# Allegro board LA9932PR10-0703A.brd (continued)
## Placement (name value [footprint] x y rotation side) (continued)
RC30  -  [R_0402]  107.06 112.4 270 top
RC31  -  [R0402_0OHM]  103.94 112.58 0 bottom
RC32  -  [R_0402]  110.62 111.48 90 top
RC33  -  [R0402_0OHM]  103.94 114.36 0 bottom
RC34  -  [R_0402]  111.51 111.48 90 top
RC35  -  [R0402_0OHM]  106.17 112.4 270 top
RC38  -  [R0402_0OHM]  140.34 111.36 90 top
RC40  -  [R0402_0OHM]  139.45 111.36 90 top
RC42  -  [R0402_0OHM]  141.23 111.36 90 top
RC44  -  [R0402_0OHM]  142.12 111.36 90 top
RC46  -  [R0402_0OHM]  143.89 111.36 90 top
RC48  -  [R0402_0OHM]  143 111.36 90 top
RC52  -  [R_0402]  106.17 114.18 270 top
RC53  -  [R_0402]  107.95 112.4 270 top
RC54  -  [R_0402]  110.62 114.56 270 top
RC55  -  [R_0402]  104.26 100.64 0 bottom
RC56  -  [R_0402]  104.85 113.47 180 bottom
RC57  -  [R_0402]  111.51 114.56 270 top
RC58  -  [R_0402]  112.52 68.71 270 top
RC59  -  [R_0402]  103.94 111.69 0 bottom
RC60  -  [R_0402]  105.17 96.83 180 bottom
RC61  -  [R_0402]  110.74 68.71 270 top
RC62  -  [R_0402]  109.73 112.4 270 top
RC63  -  [R_0402]  111.63 68.71 270 top
RC64  -  [R_0402]  104.27 98.66 90 bottom
RC66  -  [R0402_0OHM]  103.38 99.57 270 bottom
RC67  -  [R_0402]  104.26 97.72 0 bottom
RC68  -  [R_0402]  149.72 88.76 0 bottom
RC69  -  [R_0402]  150.63 89.65 180 bottom
RC73  -  [R_0402]  138.82 97.08 90 top
RC74  -  [R_0402]  134.64 113.28 180 top
RC75  -  [R_0402]  138.69 117.1 270 top
RC76  -  [R_0402]  105.17 94.23 180 top
RC77  -  [R_0402]  105.17 95.81 180 bottom
RC78  -  [R_0402]  105.17 95.11 180 top
RC79  -  [R_0402]  105.16 99.57 270 bottom
RC80  -  [R_0402]  129.48 112.12 90 top
RC81  -  [R_0402]  105.17 101.53 180 bottom
RC82  -  [R_0402]  138.42 99.43 0 top
RC83  -  [R_0402]  105.17 93.34 180 top
RC85  -  [R_0402]  151.77 97.12 180 top
RC86  -  [R_0603]  152.83 98.52 270 top
RC87  -  [R_0402]  107.96 115.05 180 top
RC88  -  [R_0402]  105.27 115.05 0 top
RC89  -  [R_0402]  150.85 98.01 0 top
RC90  -  [R_0402]  107.96 115.94 180 top
RC91  -  [R_0402]  101.72 115.31 0 bottom
RC92  -  [R0402_0OHM]  104.85 115.31 180 bottom
RC93  -  [R0402_0OHM]  104.85 116.2 180 bottom
RC94  -  [R_0402]  102.63 116.2 180 bottom
RC99  -  [R_0603]  104.97 111.56 90 top
RC100  -  [R_0402]  105.17 96 180 top
RC103  -  [R0402_0OHM]  106.55 51.67 90 top
RC104  -  [R_0402]  106.69 47.62 180 top
RC105  -  [R0603_0OHM]  152.21 96.38 90 bottom
RC106  -  [R_0603]  149.67 97.65 0 bottom
RC108  -  [R_0402]  89.46 25.45 0 top
RC109  -  [R_0402]  95.2 26.03 180 top
RC110  -  [R_0402]  99.14 23.74 180 top
RD1  -  [R0402_0OHM]  92.65 33.19 90 top
RD2  -  [R_0402]  100.9 26.77 90 top
RD3  -  [R_0402]  91.76 33.19 90 top
RD4  -  [R0402_0OHM]  100.01 27.69 270 top
RD5  -  [R_0402]  136.92 21.96 180 top
RD6  -  [R0402_0OHM]  151.63 35.68 0 top
RD7  -  [R0402_0OHM]  152.39 32.95 0 top
RD8  -  [R0402_0OHM]  93.79 21.88 90 top
RD9  -  [R_0402]  92.78 22.2 90 top
RD10  -  [R_0402]  132.4 11.98 90 top
RD11  -  [R0402_0OHM]  152.66 23.05 270 top
RD12  -  [R0402_0OHM]  153.43 18.96 90 top
RD13  -  [R0402_0OHM]  135.07 22.9 90 top
RD14  -  [R_0402]  94.68 22.8 270 top
RD15  -  [R_0402]  96.47 22.79 180 top
RD16  -  [R_0402]  95.56 21.9 0 top
RD17  -  [R_0402]  93.41 26.9 90 top
RD18  -  [R_0402]  92.99 28.69 0 top
RD19  -  [R_0402]  95.2 27.8 180 top
RD20  -  [R_0402]  102.15 24.55 270 top
RD21  -  [R_0402]  103.04 22.77 270 top
RD22  -  [R_0402]  103.04 24.55 270 top
RD23  -  [R0402_0OHM]  131.51 11.98 90 top
RD24  -  [R_0402]  99.24 24.63 0 top
RD25  -  [R0402_0OHM]  101.82 27.69 270 top
RD26  -  [R0402_0OHM]  91.62 26.98 0 top
RD27  -  [R_0402]  91.58 27.87 180 top
RD28  -  [R_0402]  97.35 21.57 90 top
RD29  -  [R0402_0OHM]  102.15 21.86 90 top
RD30  -  [R_0402]  89.21 21.9 0 top
RD31  -  [R0402_0OHM]  89.47 23.69 270 top
RE3  -  [R0402_0OHM]  192.14 12.94 0 top
RE4  -  [R0402_0OHM]  192.14 13.96 0 top
RE7  -  [R_0402]  119.57 157.76 270 bottom
RE8  -  [R_0402]  120.46 157.76 270 bottom
RE9  -  [R_0402]  121.35 157.76 270 bottom
RE10  -  [R_0402]  122.24 157.76 270 bottom
RE13  -  [R_0402]  123.13 157.76 270 bottom
RE14  -  [R_0402]  124.02 157.76 270 bottom
RE15  -  [R_0402]  124.91 157.76 270 bottom
RE16  -  [R_0402]  125.79 157.76 270 bottom
RE17  -  [R_0402]  119.61 169.89 270 top
RE18  -  [R_0402]  120.5 169.89 270 top
RE19  -  [R_0402]  121.39 169.89 270 top
RE20  -  [R_0402]  122.28 169.89 270 top
RE21  -  [R_0402]  123.17 169.89 270 top
RE22  -  [R_0402]  124.06 169.89 270 top
RE23  -  [R_0402]  124.94 169.89 270 top
RE24  -  [R_0402]  125.83 169.89 270 top
RE25  -  [R0402_0OHM]  192.14 15.1 0 top
RE26  -  [R0402_0OHM]  192.14 16.12 0 top
RE27  -  [R0402_0OHM]  195.31 30.93 0 top
RE28  -  [R0402_0OHM]  195.31 32.07 0 top
RH3  -  [R_0402]  215.6 108.03 180 bottom
RH4  -  [R_0402]  215.6 107.01 180 bottom
RH5  -  [R_0402]  177.42 127.04 90 top
RH6  -  [R_0402]  215.6 106 180 bottom
RH7  -  [R_0402]  215.6 104.98 180 bottom
RH8  -  [R_0402]  215.6 103.97 180 bottom
RH9  -  [R_0402]  215.6 102.95 180 bottom
RH10  -  [R_0402]  215.6 100.92 180 bottom
RH11  -  [R_0402]  202.36 108.67 0 bottom
RH12  -  [R_0402]  202.36 106.63 0 bottom
RH13  -  [R_0402]  202.36 107.65 0 bottom
RH14  -  [R_0402]  202.36 105.62 0 bottom
RH16  -  [R_0402]  202.36 104.6 0 bottom
RH17  -  [R_0402]  215.6 101.93 180 bottom
RH19  -  [R_0402]  202.36 103.59 0 bottom
RH20  -  [R_0402]  202.36 102.57 0 bottom
RH22  -  [R_0402]  202.36 101.55 0 bottom
RH24  -  [R_0402]  203.28 110.7 180 bottom
RH25  -  [R_0402]  202.36 109.68 0 bottom
RH26  -  [R_0402]  215.6 99.9 180 bottom
RH27  -  [R_0402]  202.36 99.14 0 bottom
RH28  -  [R_0402]  215.6 98.89 180 bottom
RH30  -  [R_0402]  215.6 97.87 180 bottom
RH31  -  [R_0402]  215.6 96.85 180 bottom
RH32  -  [R_0402]  203.28 97.11 180 bottom
RH34  -  [R_0402]  164.04 133.34 180 top
RH35  -  [R_0402]  184.33 136.48 180 bottom
RH37  -  [R_0402]  157.61 120.69 90 bottom
RH38  -  [R0402_0OHM]  182.64 125.53 180 top
RH39  -  [R_0402]  180.85 125.99 270 top
RH40  -  [R_0402]  177.92 137.72 0 top
RH42  -  [R_0402]  179.71 127.04 90 top
RH43  -  [R_0402]  181.63 131.63 180 bottom
RH44  -  [R_0402]  178.82 127.04 90 top
RH45  -  [R_0402]  186.18 136.48 180 bottom
RH46  -  [R_0603]  166.19 118.27 90 top
RH47  -  [R_0402]  167.26 124.02 270 bottom
RH48  -  [R_0402]  165.55 120.88 90 top
RH50  -  [R_0402]  166.5 120.88 90 top
RH51  -  [R0402_0OHM]  156.21 129.28 0 top
RH52  -  [R_0402]  164.72 123.17 90 top
RH53  -  [R0402_0OHM]  175.11 130.6 90 top
RH54  -  [R_0402]  165.8 124.08 270 top
RH55  -  [R_0402]  166.75 124.08 270 top
RH56  -  [R_0402]  164.59 121.8 270 top
RH57  -  [R_0402]  157.12 128.39 180 top
RH66  -  [R0402_0OHM]  164.17 118.42 180 bottom
RH67  -  [R_0402]  183.01 130.53 90 bottom
RH70  -  [R_0402]  158.83 117.72 180 bottom
RH73  -  [R_0402]  170.96 117.45 90 top
RH75  -  [R_0402]  175.39 124.21 270 bottom
RH76  -  [R_0402]  161.8 121.67 270 top
RH78  -  [R_0402]  173.61 123.3 90 bottom
RH79  -  [R_0402]  177.17 123.3 90 top
RH80  -  [R_0402]  179.52 121.14 90 top
RH81  -  [R_0402]  181.63 130.47 180 bottom
RH85  -  [R_0402]  183 129.85 0 top
RH87  -  [R_0402]  181.61 125.45 90 bottom
RH88  -  [R_0402]  174.93 151.32 270 bottom
RH89  -  [R_0402]  174.04 151.32 270 bottom
RH90  -  [R_0402]  162.69 120.76 90 top
RH91  -  [R_0402]  177.17 124.21 270 bottom
RH92  -  [R_0402]  174.5 123.3 90 bottom
RH93  -  [R_0402]  157.91 118.61 0 bottom
RH94  -  [R_0402]  173.14 151.32 270 top
RH95  -  [R_0402]  173.14 151.32 270 bottom
RH96  -  [R0402_0OHM]  153.74 151.32 270 bottom
RH97  -  [R_0402]  169.5 146.1 90 top
RH98  -  [R0402_0OHM]  155.01 134.18 270 top
RH99  -  [R_0402]  154.63 151.32 270 bottom
RH100  -  [R_0402]  154.99 132.26 0 top
RH101  -  [R0402_0OHM]  180.8 123.69 180 bottom
RH102  -  [R0402_0OHM]  169.95 119.78 0 top
RH103  -  [R0402_0OHM]  183 130.74 0 top
RH104  -  [R0402_0OHM]  178.06 123.3 90 bottom
RH105  -  [R0402_0OHM]  176.28 123.3 90 top
RH106  -  [R0402_0OHM]  170.08 117.45 90 top
RH107  -  [R0402_0OHM]  176.28 123.3 90 bottom
RH108  -  [R0402_0OHM]  171.12 125.91 0 top
RH109  -  [R0402_0OHM]  156.72 120.69 90 top
RH110  -  [R0402_0OHM]  159.39 120.69 90 top
RH111  -  [R0402_0OHM]  160.28 120.69 90 top
RH112  -  [R_0402]  176.85 121.14 90 top
RH113  -  [R0402_0OHM]  158.5 120.69 90 top
RH114  -  [R0402_0OHM]  157.61 120.69 90 top
RH118  -  [R_0402]  176.99 142.87 180 top
RH119  -  [R_0402]  183 132.58 0 bottom
RH120  -  [R_0402]  177.74 121.14 90 top
RH146  -  [R_0402]  175.81 150.41 90 bottom
RH152  -  [R0402_0OHM]  159.56 152.77 0 bottom
RH153  -  [R_0402]  160.48 153.66 180 bottom
RH155  -  [R_0402]  179.97 148.65 180 bottom
RH157  -  [R_0402]  176.99 144.64 180 top
RH158  -  [R_0402]  181.41 145.72 0 top
RH159  -  [R_0402]  177 143.75 180 top
RH160  -  [R_0402]  182.68 149.66 0 bottom
RH162  -  [R_0402]  174.63 146.35 90 top
RH163  -  [R0402_0OHM]  161.72 147.31 90 top
RH164  -  [R_0402]  179.06 147.76 0 bottom
RH165  -  [R_0402]  159.83 150.09 90 bottom
RH170  -  [R_0402]  172.7 117.45 90 top
RH174  -  [R_0402]  169.04 112.36 90 top
RH175  -  [R_0402]  169.93 112.36 90 top
RH176  -  [R_0402]  152.6 147.25 180 bottom
RH177  -  [R0402_0OHM]  215.53 139.18 180 top
RH178  -  [R0402_0OHM]  215.53 137.91 180 top
RH179  -  [R0402_0OHM]  215.53 136.64 180 top
RH180  -  [R_0402]  237.73 130.42 0 top
RH181  -  [R0402_0OHM]  215.53 135.37 180 top
RH182  -  [R0402_0OHM]  215.53 134.1 180 top
RH183  -  [R0402_0OHM]  215.53 132.83 180 top
RH184  -  [R0402_0OHM]  215.53 131.56 180 top
RH185  -  [R0402_0OHM]  214.62 130.29 0 top
RH186  -  [R_0402]  237.73 123.56 0 top
RH187  -  [R_0402]  172.45 137.28 0 top
RH188  -  [R0402_0OHM]  152.97 140.18 0 bottom
RH192  -  [R_0402]  155.95 140.64 0 top
RH195  -  [R0402_0OHM]  159.7 127.19 270 top
RH196  -  [R0402_0OHM]  185.24 134.71 0 bottom
RH202  -  [R_0402]  183.91 131.63 180 top
RH206  -  [R_0402]  156.91 123.42 90 bottom
RH216  -  [R_0402]  184.27 134.71 180 bottom
RH222  -  [R_0402]  171.82 118.37 270 top
RH223  -  [R_0402]  171.31 116.39 0 top
RH224  -  [R_0402]  163.64 120.76 90 top
RH225  -  [R_0402]  162.63 124.08 270 bottom
RH226  -  [R_0402]  163.64 124.08 270 top
RH227  -  [R_0402]  162.69 121.67 270 bottom
RH228  -  [R_0402]  159.39 121.61 270 bottom
RH229  -  [R_0402]  163.64 120.76 90 bottom
RH230  -  [R_0402]  160.28 121.61 270 bottom
RH231  -  [R_0402]  163.58 124.08 270 bottom
RH232  -  [R_0402]  175.45 132.39 0 top
RH237  -  [R_0603]  182.18 135.76 180 bottom
RH238  -  [R0603_0OHM]  180.79 134.54 0 bottom
RH240  -  [R_0603]  184.33 127.18 90 top
RH241  -  [R0603_0OHM]  183.12 127.18 90 top
RH242  -  [R0805_0OHM]  182.97 137.79 180 top
RH244  -  [R0805_0OHM]  166.53 148.39 180 top
RH245  -  [R0805_0OHM]  177.89 139.82 180 top
RH246  -  [R0603_0OHM]  156.34 152.14 0 bottom
RH255  -  [R_0402]  170.37 147.01 270 top
RH256  -  [R_0402]  171.26 147.01 270 top
RH328  -  [R_0402]  181.63 132.58 180 bottom
RH330  -  [R_0402]  175.5 146.93 0 top
RH331  -  [R_0402]  152.57 127.08 0 top
RH332  -  [R_0402]  152.57 128.12 0 top
RP1  -  [RP_0804_8P4R]  173.17 156.51 180 bottom
RP2  -  [RP_0804_8P4R]  180.9 76.57 270 top
RP3  -  [RP_0804_8P4R]  195.84 69.98 180 top
RP4  -  [RP_0804_8P4R]  189.62 57.84 90 top
RP5  -  [RP_0804_8P4R]  186.64 76.38 90 top
RP6  -  [RP_0804_8P4R]  188.01 58.99 270 top
RP7  -  [RP_0804_8P4R]  208.33 91.37 270 top
RP8  -  [RP_0804_8P4R]  211.38 91.37 270 top
RP9  -  [RP_0804_8P4R]  220.72 75.92 0 top
RP10  -  [RP_0804_8P4R]  207.98 66.85 90 top
RP11  -  [RP_0804_8P4R]  236.48 72.14 180 top
RP12  -  [RP_0804_8P4R]  235.65 75.12 180 top
RP13  -  [RP_0804_8P4R]  212.33 144.27 270 top
RP14  -  [RP_0804_8P4R]  188.69 81.05 0 top
RP15  -  [RP_0804_8P4R]  198.21 66.18 90 top
RP16  -  [RP_0804_8P4R]  195.9 75.71 270 top
RP17  -  [RP_0804_8P4R]  214.39 91.37 270 top
RP18  -  [RP_0804_8P4R]  168.61 57.76 180 top
RP19  -  [RP_0804_8P4R]  168.57 63.02 180 top
RP20  -  [RP_0804_8P4R]  208.96 147.15 270 top
RPH1  -  [RP_0804_8P4R]  167.01 118.22 180 bottom
RPH3  -  [RP_0804_8P4R]  170.26 127.88 90 top
RPH4  -  [RP_0804_8P4R]  174.8 137.44 0 top
RPH5  -  [RP_0804_8P4R]  153.8 137.74 180 top
RPH6  -  [RP_0804_8P4R]  180.34 136.12 0 top
RPH7  -  [RP_0804_8P4R]  229.69 133.91 90 top
RPH8  -  [RP_0804_8P4R]  167.07 121.26 180 bottom
RPH9  -  [RP_0804_8P4R]  167.27 127.18 90 top
RPH10  -  [RP_0804_8P4R]  180.47 138.53 180 bottom
RPH11  -  [RP_0804_8P4R]  233.99 135.06 270 top
RPH12  -  [RP_0804_8P4R]  174.62 124.58 270 top
RPH13  -  [RP_0804_8P4R]  180.34 133.14 0 top
RPH14  -  [RP_0804_8P4R]  162.36 124.07 270 top
RPH15  -  [RP_0804_8P4R]  173.12 120.57 90 top
RPH16  -  [RP_0804_8P4R]  159.38 124.07 270 top
RPH17  -  [RP_0804_8P4R]  170.55 151.95 270 bottom
RPH18  -  [RP_0804_8P4R]  203.57 119.66 0 top
RPH19  -  [RP_0804_8P4R]  186.5 136.5 90 top
RPH20  -  [RP_0804_8P4R]  152.39 125.97 0 bottom
RPH21  -  [RP_0804_8P4R]  186.58 130.99 90 top
RPV1  -  [RP_0804_8P4R]  57.79 131.61 180 bottom
RV18  -  [R0402_0OHM]  77.97 147.31 0 bottom
RV25  -  [R_0402]  66.93 131.7 270 top
RV29  -  [R_0402]  82.68 148.25 90 top
RV33  -  [R_0402]  82.03 144.83 0 top
RV36  -  [R_0402]  79.32 129.28 225 top
RV41  -  [R_0402]  59.37 137.9 90 top
RV45  -  [R_0402]  61.6 135.58 270 top
RV46  -  [R_0402]  57.6 135.3 90 top
RV47  -  [R_0402]  91.75 125.72 0 top
RV48  -  [R_0402]  73.8 139.31 180 top
RV49  -  [R_0402]  58.49 137.99 270 top
RV52  -  [R_0402]  56.19 132.9 0 bottom
RV53  -  [R_0402]  92.66 124.83 180 top
RV55  -  [R_0402]  92.66 123.94 180 top
RV56  -  [R_0402]  89.97 123.05 0 top
RV57  -  [R_0402]  91.17 118.61 0 top
RV58  -  [R_0402]  89.28 118.81 270 top
RV59  -  [R_0402]  91.94 119.56 0 top
RV60  -  [R_0402]  90.17 117.9 90 top
RV61  -  [R_0402]  89.97 123.94 0 top
RV67  -  [R_0402]  94.06 94.8 180 top
RV76  -  [R0402_0OHM]  57.34 132.9 0 top
RV77  -  [R_0402]  90.88 125.72 180 top
RV78  -  [R_0402]  61.93 147.88 180 top
RV80  -  [R_0402]  86.43 86.3 270 top
RV81  -  [R_0402]  96.14 92.31 90 top
RV82  -  [R_0402]  100.48 93.35 270 top
RV88  -  [R_0402]  56.44 129.02 0 bottom
RV100  -  [R_0402]  79.19 149.01 90 bottom
RV103  -  [R_0402]  57.34 133.89 0 top
RV104  -  [R_0402]  89.97 124.83 0 top
RV107  -  [R_0402]  92.66 104.07 180 bottom
RV108  -  [R_0402]  92.66 106.74 180 top
RV109  -  [R_0402]  81.71 112.32 0 top
RV110  -  [R_0402]  92.65 104.94 90 top
RV111  -  [R_0402]  56.19 133.79 0 bottom
RV117  -  [R_0402]  55.87 104.38 0 bottom
RV118  -  [R_0402]  54.79 100.89 0 top
RV119  -  [R_0402]  64.21 94.29 180 top
RV120  -  [R_0402]  62.44 94.29 180 top
RV125  -  [R0402_0OHM]  80.14 150.94 270 bottom
RV128  -  [R_0402]  83.49 112.32 0 top
RV129  -  [R_0402]  82.92 93.4 0 top
RV131  -  [R_0402]  84.7 93.4 0 top
RV139  -  [R_0402]  92.65 103.17 90 top
RV140  -  [R_0402]  82.92 93.4 0 bottom
RV145  -  [R_0402]  84.22 129.59 180 top
RV146  -  [R_0402]  82.43 129.01 90 top
RV147  -  [R_0402]  83.53 127.35 270 top
RV148  -  [R_0402]  84.42 128.21 180 top
RV178  -  [R_0402]  59.32 124.96 180 top
RV179  -  [R_0402]  57.53 124.97 270 top
RV180  -  [R_0402]  60.69 125.91 0 top
RV181  -  [R_0402]  84.7 93.4 0 bottom
RV182  -  [R_0402]  84.41 88.13 180 top
RV183  -  [R_0402]  93.42 103.17 270 bottom
RV184  -  [R_0402]  93.42 101.41 270 bottom
RV185  -  [R_0402]  87.96 112.32 180 top
RV186  -  [R_0402]  86.18 112.32 180 top
RV187  -  [R_0402]  92.57 102.3 0 top
RV188  -  [R_0402]  92.57 101.41 0 top
RV189  -  [R_0402]  55.7 103.05 180 top
RV190  -  [R_0402]  55.7 102.16 180 top
RV191  -  [R_0402]  66.63 112.32 180 top
RV192  -  [R_0402]  64.84 112.31 90 top
RV193  -  [R_0402]  53.91 104.84 270 top
RV194  -  [R_0402]  54.8 103.93 90 top
RV195  -  [R_0402]  59.55 112.26 0 bottom
RV196  -  [R_0402]  61.34 111.36 90 bottom
RV197  -  [R_0402]  55.88 109.73 270 bottom
RV198  -  [R_0402]  56.71 107.04 90 bottom
RV203  -  [R_0402]  64.21 93.4 180 bottom
RV205  -  [R_0402]  62.44 93.4 180 bottom
RV237  -  [R_0402]  69.15 150.43 270 bottom
RV238  -  [R_0402]  69.22 147.23 90 bottom
RV239  -  [R_0402]  73.47 148.91 270 top
RV240  -  [R_0402]  73.47 147.13 270 top
RV241  -  [R_0402]  71.06 150.5 270 bottom
RV242  -  [R_0402]  71.25 147.23 90 bottom
RV243  -  [R_0402]  67.38 149.52 90 bottom
RV244  -  [R_0402]  68.26 150.43 270 bottom
RV296  -  [R_0402]  75.82 136.59 270 top
RV298  -  [R_0402]  75.83 137.47 180 top
SW1  -  [SW_SKRBAAE010_4P]  269.14 197.91 0 top
T2  -  [TPC12]  122.99 80.97 0 top
T3  -  [TPC12]  118.95 81.8 90 top
T4  -  [TPC12]  129.96 102.66 90 top
T5  -  [TPC12]  106.15 78.21 180 bottom
T6  -  [TPC12]  120.91 84.7 0 top
T7  -  [TPC12]  145.05 98.2 0 top
T8  -  [TPC12]  145.23 114.53 180 bottom
T9  -  [TPC12]  147.08 114.56 180 bottom
T10  -  [TPC12]  127.04 104.26 90 top
T11  -  [TPC12]  106.05 73.46 180 bottom
T12  -  [TPC12]  142.95 97.92 0 top
T13  -  [TPC12]  141.94 99.22 0 top
T14  -  [TPC12]  141.67 97.16 0 top
T15  -  [TPC12]  126.14 102.71 90 top
T16  -  [TPC12]  115.7 105.69 0 top
T17  -  [TPC12]  115.29 103.67 0 top
T18  -  [TPC12]  141.02 114.52 180 bottom
T19  -  [TPC12]  106.12 108.27 0 top
T20  -  [TPC12]  143.09 114.46 180 bottom
T22  -  [TPC12]  109.51 101.04 0 top
T23  -  [TPC12]  113.97 99.48 0 top
T24  -  [TPC12]  111.95 99.6 0 top
T25  -  [TPC12]  138.95 80.71 0 top
T26  -  [TPC12]  128.93 104.82 90 top
T27  -  [TPC12]  113.67 68.76 0 top
T28  -  [TPC12]  126.99 105.74 90 top
T29  -  [TPC12]  136.97 82.04 0 top
T30  -  [TPC12]  141 92.69 0 top
T31  -  [TPC12]  128.98 84.13 0 top
T32  -  [TPC12]  131.98 84.18 0 top
T33  -  [TPC12]  149.54 72.25 180 bottom
T34  -  [TPC12]  105.98 71.55 180 bottom
T35  -  [TPC12]  141.96 95.71 0 top
T36  -  [TPC12]  140.25 94.68 0 top
T39  -  [TPC12]  134.98 102.68 0 top
T40  -  [TPC12]  133.97 101.64 0 top
T41  -  [TPC12]  128.97 101.7 0 top
T42  -  [TPC12]  127.9 102.76 0 top
T43  -  [TPC12]  132.02 101.65 0 top
T44  -  [TPC12]  112.98 101.76 0 top
T45  -  [TPC12]  114.96 101.98 0 top
T46  -  [TPC12]  140.96 90.72 0 top
T48  -  [TPC12]  126.48 107.69 0 top
T49  -  [TPC12]  113.98 91.63 0 top
T50  -  [TPC12]  136.92 102.66 0 top
T51  -  [TPC12]  115.32 88.03 0 top
T52  -  [TPC12]  105.01 108.91 180 bottom
T53  -  [TPC12]  103.93 110.14 180 bottom
T54  -  [TPC12]  107.67 107.41 0 top
T55  -  [TPC12]  114.95 100.57 90 top
T56  -  [TPC12]  114.61 111.64 0 top
T57  -  [TPC12]  156.41 127.29 0 top
T58  -  [TPC12]  154.55 127.51 0 top
T59  -  [TPC12]  178 139.32 180 bottom
T60  -  [TPC12]  151.2 150.95 180 bottom
T61  -  [TPC12]  151.03 149.63 180 bottom
T62  -  [TPC12]  152.4 149.53 180 bottom
T63  -  [TPC12]  153.67 147.56 180 bottom
T64  -  [TPC12]  161.29 145.72 0 top
T65  -  [TPC12]  160.86 133.07 0 top
T66  -  [TPC12]  152.52 151.03 180 bottom
T67  -  [TPC12]  162.07 134.09 0 top
T68  -  [TPC12]  168.76 131.28 0 top
T71  -  [TPC12]  165.58 130.83 0 top
T72  -  [TPC12]  117.99 99.69 0 top
T75  -  [TPC12]  167.77 133.37 0 top
T76  -  [TPC12]  165.73 145.12 0 top
T77  -  [TPC12]  166.89 144.13 0 top
T78  -  [TPC12]  152.72 146.29 180 bottom
T79  -  [TPC12]  153.35 146.29 180 bottom
T80  -  [TPC12]  154.05 145.66 180 bottom
T81  -  [TPC12]  153.42 145.66 180 bottom
T82  -  [TPC12]  170.76 142.61 0 top
T83  -  [TPC12]  172.42 142.62 0 top
T84  -  [TPC12]  153.1 141.21 180 bottom
T85  -  [TPC12]  158.24 139.94 90 top
T86  -  [TPC12]  158.04 126.7 0 top
T87  -  [TPC12]  172.91 136.13 90 top
T88  -  [TPC12]  113.96 103.08 0 top
T89  -  [TPC12]  111.48 105.68 0 top
T90  -  [TPC12]  111.98 103.7 0 top
T105  -  [TPC12]  65.81 133.62 0 top
T106  -  [TPC12]  62.03 132.64 0 top
T108  -  [TPC12]  65.79 131.41 0 top
T116  -  [TPC12]  107.58 103.91 0 top
T117  -  [TPC12]  109.89 104.59 0 top
T118  -  [TPC12]  107.04 105.48 0 top
T122  -  [TPC12]  193.05 74.72 0 top
T131  -  [TPC12]  83.44 121.91 0 top
T132  -  [TPC12]  57.53 145.02 180 bottom
T133  -  [TPC12]  85.16 145.85 180 bottom
T142  -  [TPC12]  236.03 163.29 90 top
T143  -  [TPC12]  236.03 162.51 90 top
T146  -  [TPC12]  179.2 65.84 0 top
T147  -  [TPC12]  186.63 74.79 0 top
T151  -  [TPC12]  67.12 147.06 180 bottom
T152  -  [TPC12]  65.85 147.88 180 bottom
T156  -  [TAIMA_IH-115-F_24P]  259.26 187.43 90 top
T157  -  [TPC12]  108.61 94.47 0 top
T158  -  [TPC12]  110.01 94.91 0 top
T159  -  [TPC12]  108.55 99.49 0 top
T160  -  [TPC12]  106.11 97.78 180 bottom
T161  -  [TPC12]  111.93 94.49 0 top
T162  -  [TPC12]  106.64 99.55 0 top
T163  -  [TPC12]  106.58 102.61 0 top
T164  -  [TPC12]  107.44 101.07 0 top
T165  -  [TPC12]  108.45 102.56 0 top
T166  -  [TPC12]  105.7 100.74 0 top
T167  -  [TPC12]  108.65 96.18 0 top
T168  -  [TPC12]  108.79 98.2 0 top
T169  -  [TPC12]  111.96 95.9 0 top
T170  -  [TPC12]  106.66 98.06 0 top
T173  -  [TPC12]  108.89 105.9 0 top
T174  -  [TPC12]  112.98 104.82 0 top
U2  -  [SLGC55584AVTR_TDFN8_2X2]  275.07 185.01 180 top
U6  -  [PI3V713-AZLEX_TQFN32_6X3]  136.72 156.3 270 bottom
U8  -  [RT9818A-44GU3_SC70-3]  173.23 115.94 90 top
U9  -  [NL17SZ08DFT2G_SC70-5]  176.34 118.69 270 top
U15  -  [NL17SZ08DFT2G_SC70-5]  257.43 174.63 270 top
U19  -  [PS8401ATQFN40GTR-A3_TQFN40_5X5]  16.68 197.4 0 top
U20  -  [PI3C3125LEX_TSSOP14]  165.82 158.34 270 top
U21  -  [TC7SET04FU_SSOP5]  169.11 159.87 90 top
U23  -  [PI3C3125LEX_TSSOP14]  179.62 154.44 90 top
U24  -  [TC7SET04FU_SSOP5]  177.88 160.76 90 top
U27  -  [RTD2136S-CG_QFN48_6X6]  198.45 165.32 270 top
U31  -  [WGI217LM-QPN9-A2_QFN48_6X6]  243.2 161.68 90 top
U32  -  [PI3L720ZHEX_TQFN42_9X3P5]  246.26 177.4 0 top
U36  -  [TPS22966DPUR_SON14_2X3]  227.66 69.85 90 top
U37  -  [TPS22966DPUR_SON14_2X3]  173.55 41.26 0 top
U38  -  [OZ777FJ2LN_QFN48_6X6]  183.34 28.86 270 top
U39  -  [AT97SC3204-X2A14-AB_TSSOP28]  217.21 113.19 180 top
U41  -  [TPS2231MRGPR-2_QFN20_4X4]  235.63 64.96 180 top
U46  -  [ECE5048-LZY_DQFN132_11X11]  191.32 64.06 90 top
U48  -  [G547I2P81U_MSOP8]  281.66 192.24 0 top
U50  -  [NL17SZ08DFT2G_SC70-5]  200.02 89.26 90 top
U51  -  [MEC5075-LZY_DQFN132_11X11]  205.93 73.34 0 top
U52  -  [W25Q64FVSSIQ_SO8]  235.47 127.88 90 top
U53  -  [W25Q32FVSSIQ_SO8]  235.47 121.76 90 top
U54  -  [NL17SZ08DFT2G_SC70-5]  217.17 157.39 90 top
U56  -  [NL17SZ08DFT2G_SC70-5]  214.25 154.53 90 top
U57  -  [TPS22966DPUR_SON14_2X3]  245.31 148.96 0 top
U58  -  [NL17SZ08DFT2G_SC70-5]  227.27 113.06 270 top
U74  -  [ALC3226-CG_QFN48_7X7]  267.99 159.97 270 top
U88  -  [LNG3DMTR_LGA16_3X3]  83.65 51 0 top
U89  -  [AP2330W-7_SC59-3]  25.47 204.46 90 top
U91  -  [G547I2P81U_MSOP8]  282.17 181.88 270 top
U93  -  [G547I2P81U_MSOP8]  279.12 169.43 270 top
U145  -  [TPS22966DPUR_SON14_2X3]  264.05 175.69 0 top
U146  -  [TPS22966DPUR_SON14_2X3]  220.67 126.47 90 top
U148  -  [APL3512ABI-TRG_SOT23-5]  196.66 172.35 180 top
UC1  -  [74AHC1G09GW_TSSOP5]  104.13 48.94 0 top
UC2  -  [SN74LVC1G07DCKR_SC70-5]  101.45 95.53 90 bottom
UC3  -  [74AHC1G09GW_TSSOP5]  160.15 116.94 90 bottom
UH1  -  [DH82LPMS-QCG1-B0_FCBGA_695P]  175.8 128.04 90 bottom
UH2  -  [NL17SZ08DFT2G_SC70-5]  179.27 127.34 0 bottom
UH3  -  [NL17SZ08DFT2G_SC70-5]  160.28 119.58 270 top
UV1  -  [216-0841009-A0-SUN_FCBGA_631P]  60.58 123.4 0 bottom
UV3  -  [K4G41325FC-HC04_FBGA_170P]  69.46 96.46 180 top
UV4  -  [K4G41325FC-HC04_FBGA_170P]  79 109.26 0 top
UV5  -  [K4G41325FC-HC04_FBGA_170P]  79 96.46 0 bottom
UV6  -  [K4G41325FC-HC04_FBGA_170P]  69.46 109.26 180 bottom
UV14  -  [74AHC1G09GW_TSSOP5]  83.81 146.92 0 top
Y3  -  [Y_X3G025000DI1H-H_4P]  248.88 163.99 90 top
Y6  -  [Y_Q13FC1350000_2P]  198.71 72.63 0 top
YH1  -  [Y_Q13FC1350000_2P]  184.51 123.94 180 top
YH2  -  [Y_Q22FA2380049900_4P]  158.73 157.44 0 bottom
YV1  -  [Y_7V27000050_4P]  77.55 148.81 180 bottom

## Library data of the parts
C7 C1552 CC24-CC33 CC36-CC48 CH28 PC8 PC13 PC109 PC110 PC202 PC203 PC207 PC208 PC304 PC305 PC310 PC512-PC514 PC533-PC535 PC603 PC604 PC621 PC622 PC707 PC712-PC714 PC718 PC719 PC724 PC728 PC731 PC732 PC734 PC737-PC739 PC807 PC900-PC904 PC909-PC914 PC917-PC926 PC935-PC943 PC963-PC966 PC970-PC972 = C_0805
C8 C9 C16 C18 C25-C32 C46 C100 C101 C103-C105 C107 C108 C110-C112 C114 C116-C118 C283-C287 C290 C302 C306 C340 C342 C344 C354 C355 C399 C402 C416-C419 C435-C438 C444 C445 C448 C450 C451 C454 C482 C500 C501 C580 C581 C628-C631 C636 C675 C724 C740 C757 C774-C777 C780 C781 C800 C802 C968 C972 C998 C1002 C1004 C1107 C1167 C1184 C1216 C1501 C1503 C1505 C1506 C1508-C1510 C1518 C1519 C1524 C1526 C1533 C1534 C1539 C1541 C1551 C1553-C1559 CC17-CC19 CC21 CC138 CD45-CD48 CE5 CE7 CE10-CE18 CH6 CH7 CH10-CH14 CH17 CH22-CH25 CH27 CH29 CH37 CH40 CH53 CH76 CV18-CV26 CV52 CV54 CV57 CV61 CV62 CV67 CV71 CV75 CV80 CV82 CV83 CV92-CV95 CV151-CV159 CV162-CV164 CV166 CV167 CV182 CV185 CV199 CV203 CV204 CV215 CV219 CV220 CV222 CV223 CV225 CV322-CV333 CV340-CV344 CV349-CV358 CV411 PC5 PC17 PC103 PC105 PC106 PC205 PC209 PC211 PC214 PC215 PC302 PC303 PC307 PC401 PC402 PC405-PC407 PC500 PC510 PC515 PC516 PC518 PC520 PC521 PC525-PC528 PC536 PC539-PC541 PC545-PC548 PC600 PC602 PC611-PC616 PC624 PC627 PC630 PC632 PC665-PC668 PC674 PC675 PC704 PC705 PC708 PC710 PC716 PC721-PC723 PC725-PC727 PC729 PC730 PC733 PC736 PC801 PC805 PC808-PC810 PC812 PC814 PC817 PC927-PC934 PC944-PC951 = C_0402
C44 C45 C550-C553 = C_0402: room: TPM
C47 C106 C109 C113 C115 C246 C247 C423 C439 C443 C446 C447 C449 C452 C453 C455 C479-C481 C483 C484 C578 C639 C676 C779 C782 C783 C967 C969 C1214 C1247 C1502 C1504 C1507 C1525 C1540 CC137 CD12 CH20 CH21 CH38 CV56 CV58-CV60 CV66 CV84 CV98 CV201 CV216 CV221 CV224 CV274 CV275 CV423 PC3 PC12 PC14 PC111 PC112 PC114 PC116-PC120 PC206 PC210 PC212 PC213 PC306 PC308 PC309 PC400 PC403 PC404 PC509 PC511 PC522 PC524 PC529 PC538 PC542 PC543 PC601 PC605 PC607 PC608 PC610 PC617-PC619 PC623 PC626 PC631 PC660-PC664 PC669 PC670 PC672 PC680 PC700 PC703 PC706 PC709 PC715 PC717 PC720 PC735 PC811 PC813 PC815 PC816 PC818-PC820 = C_0603
C50 C1001 = C_0402: room: IO
C51-C53 = C_0402: room: USH
C288 C289 C720-C722 C725 C727 C733-C737 C739 C741-C744 = C_0402: room: KBC
C296 = C_0603: room: LVDS
C297 C298 = C_0402: room: LVDS
C299 C301 = C_0402: room: CAM
C300 = C_0603: room: CAM
C346-C353 = C_0402: room: HDMI
C356 C357 C360 C365-C369 = C_0402: room: DP_SW
C383-C386 C388 C395 C396 = C_0402: room: HDD
C387 = C_0603: room: HDD
C397 C398 C404-C409 = C_0402: room: ODD
C458-C461 C463 C466-C474 C478 = C_0402: room: LAN
C462 C464 = C_0603: room: LAN
C485 = C_1808
C559-C561 C564 C566 C572 C577 = C_0603: room: OZ600
C567-C569 C571 C574-C576 = C_0402: room: OZ600
C595 C596 C598 C603-C607 = C_0402: room: WLAN
C608 = C_0603: room: WLAN
C610-C612 C614 = C_0402: room: WWAN
C613 = C_0805: room: WWAN
C615 = C_D2: room: WWAN
C616 = C_0402: room: SIM
C617 C618 C621-C625 = C_0402: room: WPAN
C626 = C_0603: room: WPAN
C633-C635 C637 C640 C642 C645 C646 C649 = C_0402: room: EXPRESS
C638 C641 C643 = C_0603: room: EXPRESS
C651 = C_APXK6R3ARA221MF451: room: USB
C654 C715 = C_0402: room: USB
C679-C701 = C_0402: room: DOCKING
C702 C703 = C_0603: room: DOCKING
C705 C714 = C_0603: room: SIO
C706-C710 C716 = C_0402: room: SIO
C746 = C_0402: room: FLASH ROM
C755 C759 = C_0402: room: TOUCH.PAD
C756 C758 = C_0402: room: KB
C764 = C_0603: room: +3V_5V_RUN SOURCE
C765 = C_0603: room: +3.3V_SUS SOURCE
C772 = C_0603: room: +1.05VRUN_SOURCE
C773 = C_0402: room: +1.05VRUN_SOURCE
C778 = C_0402: room: LED
C952 C954-C956 C962 C963 C965 = C_0603: room: CODEC
C957 C959 C961 C973-C977 C994 C1105 C1106 = C_0402: room: CODEC
C958 C960 = C_0805: room: CODEC
C1177 C1178 = C_0805: room: LAN
C1523 C1538 = C_B2
CC1-CC16 = C_0402: room: CPU
CC34 CC35 PC606 PC628 PC629 PC677 = C_D2
CD1-CD6 CD15-CD28 CD37-CD44 = C_0402: room: MEMORY
CD7-CD11 CD13 CD29-CD35 = C_0603: room: MEMORY
CD14 CD36 = C_APXK2R5ARA331MF451: room: MEMORY
CE6 = C_0805: room: DOCKING
CH2 CH4 CH5 CH18 CH19 CH30 CH34-CH36 CH43-CH51 CH54-CH57 CH59-CH62 CH64-CH75 = C_0402: room: PCH
CH52 CH63 = C_0603: room: PCH
CMOS1 ME1 = SHORTPADS: User Part Number: PART#; room: PCH
CV1-CV17 CV49 CV53 CV55 CV68 CV69 CV73 CV74 CV76-CV79 CV81 CV85-CV87 CV129-CV131 CV133 CV134 CV137-CV150 CV165 CV176-CV181 CV188 CV189 CV191 CV192 CV198 CV207-CV210 = C_0402: room: GPU
CV41-CV44 CV70 CV72 CV202 = C_0603: room: GPU
D1 D35 D36 D71 = RB751V40_SC76-2
D7 D9 D10 = BAT54CW_SOT323-3
D31 = RB751V40_SC76-2: room: WLAN
D32 = RB751V40_SC76-2: room: DOCKING
D33 = L30ESD24VC3-2_SOT23-3: room: DOCKING
D59 D62 = RB751V40_SC76-2: room: LED
D72 = L30ESDL5V0C3-2_SOT23-3: room: USB
D78 = TVWDF1004AD0_DFN9: room: USB
D81 D82 = L03ESDL5V0CC3-2_SOT23-3
D86 = PESD5V0U2BT_SOT23-3
D88 D91 = TVWDF1004AD0_DFN9
D89 D90 = L30ESDL5V0C3-2_SOT23-3
FD1-FD4 = FIDUCIAL_C40M80: room: LED
H1 H2 = H_3P8: room: LED
H3 H5 H6 H9 H15 H16 = H_3P3: room: LED
H4 H8 H10 H12 H13 = H_3P0: room: LED
H7 H11 H20 = H_3P0
H14 = H_3P2: room: LED
H17 = H_2P0N: room: LED
H18 H19 = H_2P3
H21 = H_3P1X2P1N
H22 H23 = H_3P3
JAPS1 = TYCO_1-2041070-6_16P
JCAM1 = E-T_3702K-Q08C-07L_8P: room: CAM
JCPU1 = LOTES_AZIF0012-P002B_947P-T: room: CPU
JDEG2 = HB_A531015-SCHR21_10P: room: KBC
JDIMM1 = TYCO_2-2013290-1_204P: room: MEMORY
JDIMM2 = TYCO_2-2013311-1_204P: room: MEMORY
JDOCK1 = JAE_WD2F144WB1R300_144P: room: DOCKING
JEXP1 = E-T_1001K-F30C-03L_30P-T: room: EXPRESS
JFAN1 = ACES_50273-0040N-001_4P: room: FAN
JHDMI1 = CONCR_099ATAC19NBLCNF_19P: room: HDMI
JHP1 = SINGA_2SJ3082-000111F_6P-T
JIO1 = E-T_1000K-Y40E-02L_40P: room: IO
JKB1 = HB_A091020-SAHR22_10P: room: KB
JLED1 = HB_A520620-SCHR22_6P
JLOM1 = J-L_TNBNRBC80002008_13P-T
JLVDS1 = ACES_59003-04006-001_40P
JMDIA1 = HB_A520620-SCHR22_6P: room: IO
JMINI1 = BELLW_80003-8041_52P
JMINI2 = BELLW_80003-8041_52P: room: WLAN
JMINI3 = BELLW_80003-1121_52P: room: WPAN
JRTC1 = ACES_50273-0020N-001_2P
JSATA1 = SANTA_196003-1_22P: room: HDD
JSATA2 = TYCO_2-2129116-3_31P-T: room: ODD
JSD1 = ALPS_SCDACA0101_19P: room: OZ600
JSF1 = HB_A090620-SAHR21_6P
JSIM1 = T-SOL_159-1000302602_10P-T: room: SIM
JSPI1 = TYCO_2-2041070-0_20P-T: room: FLASH ROM
JSPK1 = ACES_50273-0040N-001_4P: room: CODEC
JTAG1 = SHORTPADS: User Part Number: PART#; room: KBC
JTCH1 = ACES_50228-0067N-001_6P
JTP1 = HB_A520820-SCHR22_8P: room: TOUCH.PAD
JUSB1 = SANTA_373130-1_9P: room: USB
JUSB2 = LOTES_ABA-USB-116-P04_9P: room: USB
JUSB3 = LOTES_ABA-USB-116-P04_9P
JUSH1 = HB_A522020-SCHR22_20P: room: USH
JXDP1 = MOLEX_52435-2671_26P-T: room: XDP1
JXDP2 = SAMTE_BSH-030-01-L-D-A_60P: room: XDP2
L1-L4 L99 L108 L109 L111 L112 LE2 LE4 LE5 = MURAT_DLW21SN900HQ2L_0805_4P
L10 = MURAT_DLW21SN121SQ2L_4P: room: CAM
L11 L107 L110 = MURAT_DLW21SN900SQ2L_0805_4P
L13 = MURAT_BLM15BB221SN1D_2P
L29 = TAIYO_CBC2012T4R7M_2P: room: LAN
L45 L47 = MURAT_BLM15BD601SN1D_2P: room: OZ600
L51 = MURAT_DLW21SN900SQ2L_0805_4P: room: USB
L77 = MURAT_BLM15PX600SN1D_2P: room: CODEC
L95 L96 = MURAT_DLW21SN900HQ2L_0805_4P: room: USB
L702-L705 = MURAT_BLM18PG330SN1D_2P
L706 L707 = MURAT_BLM15BD601SN1D_2P
LED1 = LED_LTW-193ZDS5_2P: room: LED
LH1 = MURAT_BLM18PG181SN1D_2P: room: PCH
LV16-LV19 LV21 LV30 PH500 PH501 PH600 PH601 PR1 PR6 PR10-PR16 PR18 PR20 PR23 PR25 PR100-PR102 PR104-PR106 PR111 PR119 PR201 PR204-PR207 PR209 PR300 PR302 PR303 PR305-PR307 PR402 PR403 PR405 PR500 PR503 PR504 PR507 PR509 PR512 PR519 PR521 PR525 PR528-PR530 PR533 PR535 PR537 PR539 PR543-PR546 PR549 PR551 PR555 PR556 PR558 PR602 PR604 PR605 PR607 PR608 PR610 PR612 PR615 PR616 PR619 PR623 PR624 PR626 PR627 PR631-PR634 PR638-PR640 PR642 PR644 PR645 PR648 PR651 PR652 PR654-PR656 PR659 PR683 PR684 PR687 PR689 PR691 PR692 PR697 PR703 PR706 PR707 PR713 PR714 PR720 PR722 PR723 PR725-PR728 PR730-PR736 PR738-PR741 PR743 PR744 PR746-PR748 PR801 PR802 PR804 PR807 PR808 PR810 PR813-PR819 PR822-PR824 PR826-PR830 PR833 PR834 PR839 PR840 PR844 PR846 PR849 PR858 PR863 PR864 PR869 PR870 PR874 PR875 PR881 PR883-PR885 PR894 R7 R30 R38 R39 R51 R52 R55 R61-R65 R68-R82 R85-R88 R100 R101 R105-R108 R114 R153 R392 R407 R415 R424 R431-R433 R517 R558 R566 R571-R574 R657 R695 R806 R864 R874 R888 R952 R1069 R1088 R1100 R1119 R1120 R1139 R1141 R1142 R1145 R1146 R1166 R1167 R1624 R1629 R1630 R1635 R1636 R1640 R1642 R1653 R1654 R1667 R1668 R1676 R1677 R1679 R1700 R1702 R1703 R3664-R3666 R3668 R3669 R3671 R3689-R3691 R3696-R3698 R3710 R3711 R3721 R3722 R3727 R3728 R3737 R3761 R3771 R3773 R3884-R3886 RC11-RC13 RC20-RC22 RC30 RC34 RC55 RC58 RC59 RC62 RC69 RC75-RC77 RC80 RC81 RC83 RC85 RC87-RC91 RC94 RC104 RC108-RC110 RD9 RD10 RD14 RD16-RD22 RD24 RD27 RD28 RD30 RE7-RE10 RE13-RE24 RH32 RH34 RH37 RH54-RH57 RH67 RH70 RH73 RH81 RH85 RH88-RH90 RH92 RH93 RH95 RH119 RH146 RH153 RH155 RH157 RH159 RH162 RH165 RH175 RH176 RH180 RH186 RH187 RH192 RH202 RH206 RH216 RH222-RH232 RH255 RH328 RH330-RH332 RV25 RV48 RV81 RV82 RV88 RV100 RV103 RV104 RV128 RV129 RV131 RV139 RV140 RV145-RV148 RV178-RV198 RV203 RV205 RV237-RV244 RV296 RV298 = R_0402
PBATT1 = OCTEK_BTJ-09WKFB_9P
PC101 PC102 = C_APXK6R3ARA221MF451
PC201 PC301 = C_APXK2R5ARA331MF451
PC216 = C_SX
PC530-PC532 = C_EEEFK1E101YP
PC905-PC908 PC916 = C_D1
PD2 PD4 = TVNST52302AB0_SOT523-3
PD3 = BAS40-05W_SC70-3
PD7 PD807 PD811 PD818-PD821 = SDMK0340L-7-F_SOD323-2
PD700 = SBR3A40SA-13_SMA2
PD701 PD810 PD813 PD815 = RB717F_SOT323-3
PD702 = RB751V-40_SOD323-2
PD800 PD806 PD808 = PDS5100H-13_POWERDI5-3
PJP1 PJP101-PJP103 PJP200 PJP203 PJP204 PJP301 PJP500 PJP600 PJP700 = JUMP_43X118
PJP2 PJP63 PJP67 PJP201 PJP202 PJP602 PJP701 = JUMP_43X39
PJP3 = JUMP_43X79: room: +5V_HDD SOURCE
PJP4 = JUMP_43X79: room: +5VMOD SOURCE
PJP53 PJP64 = JUMP_43X39: room: HDD
PJP60 PJP100 PJP300 PJP400 PJP401 PJP609-PJP612 PJP702 = JUMP_43X79
PJP61 = JUMP_43X39: room: TPM
PJP62 PJP65 = JUMP_43X39: room: CODEC
PJPDC1 = JESS_UCNR2451M005-0_5P
PL2 PL3 = TAIYO_FBMJ4516HS720NT_2P
PL4 = MURAT_BLM15AG102SN1D_2P
PL5 = KC_FBMA-L18-453215_L1812_2P
PL101 = CYNTE_PCMB063T-2R2MS_2P
PL102 = CYNTE_PCMB063T-3R3MS_2P
PL103 PL701 = CYNTE_PCMB053T-1R0MS_2P
PL201 = TOKO_FDUE1040D-1R0M-P3_2P
PL301 = TOKO_FDSD0630-H-1R0M-P3_2P
PL401 = CYNTE_PH041H-1R0MS_2P
PL502 PL503 PL600 PL601 = NEC_MPC0740LR42C_2P
PL504 PL602 = L_1812-1806
PL603 = TOKO_FDSD0420-H-1R0M-P3T_2P
PL700 = TOKO_FDVE1040-H-5R6M-P3_2P
PQ1 PQ816 = FDV301N_NL_SOT23-3
PQ2 = MMST3904-7-F_SOT323-3
PQ4 PQ810 PQ811 PQ815 PQ826 = FDS6679AZ_SO8
PQ6 = IMD2AT-108_SC74-6
PQ7 PQ801 PQ814 PQ822 PQ823 PQ828 PQ830 = FDN338P_NL_SOT23-3
PQ101 PQ102 PQ301 = SIS412DN-T1-GE3_POWERPAK8-5
PQ103 PQ104 PQ303 = SI7716ADN-T1-GE3_POWERPAK8-5
PQ201 PQ505 PQ509 PQ704-PQ706 PQ711 = SIR472DP-T1-GE3_POWERPAK8-5
PQ203 = SIR818DP-T1_POWERPAK-SO8-5
PQ508 PQ512 = SI7170DP-T1-GE3_POWERPAK8-5
PQ600 PQ601 = CSD86350Q5D_SON8
PQ610 = SSM3K7002FU_SC70-3
PQ700 PQ800 PQ809 = SI4835BDY-T1-E3_SO8
PQ701 PQ702 = NTR4502PT1G_SOT23-3
PQ703 = NTGD4161PT1G_TSOP6
PQ707 PQ805-PQ807 PQ812 PQ813 PQ819 PQ821 PQ824 = 2N7002DW-T-R7_SOT363-6
PQ709 PQ710 PQ802 PQ817 PQ818 PQ825 PQ827 PQ829 PQ831 = RHU002N06_SOT323-3
PR22 PR401 PR680 PR835 = R_0805
PR26 PR103 PR110 PR118 PR208 PR210 PR211 PR308 PR309 PR406 PR511 PR520 PR524 PR526 PR548 PR600 PR618 PR620 PR621 PR625 PR628 PR629 PR635 PR643 PR650 PR657 PR681 PR688 PR700 PR702 PR704 PR705 PR709 PR710 PR717-PR719 PR724 PR737 PR745 PR811 PR812 PR832 PR838 PR843 PR847 PR850 PR857 PR862 PR866 PR868 PR882 PR886 PR887 PR890 PR895 R5 R6 R15 R40 R104 R152 R429 R575-R578 R830 R834 R839 R866 R1070 R1169 R1607 R1672 R1673 R3731 R3732 R3772 RC31 RC33 RC38 RC92 RC93 RC103 RD6 RD7 RD11-RD13 RD23 RD25 RD26 RD29 RD31 RE3 RE4 RE25-RE28 RH51 RH96 RH101 RH110 RH179 RH182 RH184 RH185 RH188 RH195 RH196 RV76 RV125 = R0402_0OHM
PR107 PR108 PR200 PR203 PR301 PR534 PR536 PR538 PR550 PR552 PR553 PR614 PR649 PR715 PR821 RC86 RC106 RH237 RH240 = R_0603
PR109 PR112 PR202 PR304 PR541 PR554 PR622 PR653 PR721 PR742 = R_1206
PR701 PR716 = R_1206_4P-D
PR831 PR854 PR877 R3881-R3883 RH242 RH244 RH245 = R0805_0OHM
PRP2 RP1-RP20 RPH1 RPH3-RPH21 RPV1 = RP_0804_8P4R
PU1 = TS5A63157DCKR_SC70-6
PU100 = TPS51225CRUKR_QFN20_3X3
PU200 = RT8207MZQW_WQFN20_3X3
PU300 = TPS51212DSCR_SON10_3X3
PU400 = SY8033BDBC_DFN10_3X3
PU500 = ISL95812HRZ-T_QFN32_4X4
PU600 = ISL62883CHRTZ-T_TQFN40_5X5
PU602 = SY8036DBC_DFN10_3X3
PU603 = G971ADJF11U_SO8
PU700 = BQ24738RGRR_QFN20_3P5X3P5
PU701 = LM393DR_SO8
PU703 = INA199A2DCKR_SC70-6
PU704 PU801 PU804-PU808 = TC7SH08FU_SSOP5
PU800 = CD3301RHHR_QFN36_6X6
Q1-Q4 QV7 = PMST3904_SOT323-3
Q21 = FDC654P-G_SSOT-6: room: LVDS
Q22 = L2N7002WT1G_SC-70-3: room: LVDS
Q23 = DMG2301U-7_SOT23-3: room: CAM
Q24 Q77 Q89 Q100 Q324 Q326 QC5 QD7 QD9 QH3 QV5 QV6 QV11 = L2N7002WT1G_SC-70-3
Q29 = DMN66D0LDW-7_SOT363-6: room: HDD
Q32 = PMV65XP_SOT23-3
Q45 Q47 = L2N7002WT1G_SC-70-3: room: KBC
Q48 = L2N7002WT1G_SC-70-3: room: USB
Q52 = DMN66D0LDW-7_SOT363-6: room: +1.5V_RUN_SOURCE
Q59 = L2N7002WT1G_SC-70-3: room: +1.5V_RUN_SOURCE
Q63 = AO4354_SOIC-8: room: +1.05VRUN_SOURCE
Q70-Q72 = L2N7002WT1G_SC-70-3: room: DISCHARGE
Q74 Q83 Q84 = DMN66D0LDW-7_SOT363-6: room: LED
Q75 Q79 Q81 = PDTA114EU_SC70-3: room: LED
Q76 Q123 = DMN66D0LDW-7_SOT363-6: room: ODD
Q106 = DMN66D0LDW-7_SOT363-6: room: CODEC
Q124 = DMN66D0LDW-7_SOT363-6: room: WLAN
Q325 Q330 Q331 QD6 = DMN66D0LDW-7_SOT363-6
QC1 = L2N7002WT1G_SC-70-3: room: CPU
QC3 = L2N7002WT1G_SC-70-3: room: +1.5V_CPU_VDDQ SOURCE
QH2 = BSS138W-7-F_SOT323-3: room: PCH
QH4 = DMN66D0LDW-7_SOT363-6: room: PCH
QV1 = AO4354_SOIC-8: room: GPU
QV2 = L2N7002WT1G_SC-70-3: room: GPU
QV3 QV8 = PMST3904_SOT323-3: room: GPU
QV4 = MMBT3906WT1G_SC70-3: room: GPU
QV12 = DMG2301U-7_SOT23-3
R154 R1658 R3735 R3736 R3762-R3770 RC105 RH238 RH241 RH246 = R0603_0OHM
R159 R160 R422 R423 R1137 R1138 = R_0402: room: LVDS
R416 = R_0402: room: CRT
R418 R420 R811 R812 R817 R825 R836 R843 R850 R871 R872 R875 R879 R884 R887 R1171 R1179 R1622 R1623 = R_0402: room: KBC
R427 R428 = R_0402: room: CAM
R491 R492 = R_0402: room: DP_SW
R501-R503 R506 R508 = R_0402: room: HDD
R512 = R_0402: room: +5VMOD SOURCE
R515 = R_0402: room: ODD
R545 R546 R549 R553 R557 R561 R562 = R_0402: room: LAN
R551 R552 R555 R1144 R1187 = R0402_0OHM: room: LAN
R585 R589 = R_0402: room: USH
R676 R677 = R_0402: room: OZ600
R693 R706 R1620 = R_0402: room: WLAN
R694 R719 R725 R726 = R_0402: room: WWAN
R703 R707 = R0402_0OHM: room: WLAN
R704 = R0402_0OHM: room: WWAN
R717 = R0402_0OHM: room: EXPRESS
R731 R732 R734 = R_0402: room: EXPRESS
R733 = R_0402: room: WPAN
R736 R740 R816 R1603-R1606 R1614 = R_0402: room: USB
R738 R802 = R0402_0OHM: room: SIO
R755 R757 R758 = R_0402: room: DOCKING
R772 R793 R796 R800 R803 R804 R807 R1154 = R_0402: room: SIO
R853 R1068 R1180 = R0402_0OHM: room: KBC
R894 R901 R936 = R_0402: room: FLASH ROM
R902 R903 = R_0402: room: TOUCH.PAD
R909 = R_0402: room: +1.5V_RUN_SOURCE
R925 R926 = R_0402: room: DISCHARGE
R927 = R_0603: room: DISCHARGE
R930 R931 R1611 = R_0402: room: +1.05VRUN_SOURCE
R932 R934 R937 R938 R949 R951 R953 R955 R957 R958 = R_0402: room: LED
R1076 R1079-R1082 R1086 R1096 R1097 R1099 = R_0402: room: CODEC
R1095 = R0805_0OHM: room: CODEC
R1161 = R0603_0OHM: room: TOUCH.PAD
R1162 = R_0603: room: TOUCH.PAD
R1626 = R0402_0OHM: room: USB
RC1 RC15 RC16 RC23 RC24 RC27-RC29 RC32 RC52-RC54 RC56 RC57 RC60 RC61 RC63 RC64 RC67 RC68 RC78 RC100 = R_0402: room: CPU
RC5-RC7 RC9 = R_0402: room: XDP1
RC10 RC35 RC40 RC42 RC44 RC46 RC48 RC66 = R0402_0OHM: room: CPU
RC73 RC74 RC79 RC82 = R_0402: room: +1.5V_CPU_VDDQ SOURCE
RC99 = R_0603: room: CPU
RD1 RD4 RD8 = R0402_0OHM: room: MEMORY
RD2 RD3 RD5 RD15 = R_0402: room: MEMORY
RH3-RH10 RH12-RH14 RH16 RH17 RH19 RH20 RH24 = R_0402: room: XDP2
RH11 RH22 RH25-RH28 RH30 RH31 RH35 RH39 RH40 RH42-RH45 RH47 RH48 RH50 RH52 RH75 RH76 RH78-RH80 RH87 RH91 RH94 RH97 RH99 RH100 RH112 RH118 RH120 RH158 RH160 RH164 RH170 RH174 RH256 = R_0402: room: PCH
RH38 RH53 RH66 RH98 RH102-RH105 RH111 RH113 RH114 RH152 RH163 RH177 RH178 RH181 RH183 = R0402_0OHM: room: PCH
RH46 = R_0603: room: PCH
RH106-RH109 = R0402_0OHM: room: XDP1
RV18 = R0402_0OHM: room: GPU
RV29 RV33 RV36 RV41 RV45-RV47 RV49 RV52 RV53 RV55-RV61 RV67 RV77 RV78 RV80 RV107-RV111 RV117-RV120 = R_0402: room: GPU
SW1 = SW_SKRBAAE010_4P: room: SWITCH
T2-T8 T11 T13 T15-T20 T22-T36 T40-T46 T48-T52 T54 T55 T60 T61 T64-T68 T71 T72 T75-T90 T105 T116 T118 T122 T131-T133 T146 T147 T151 T152 T157-T170 T173 T174 = TPC12
T9 T10 T12 T14 T39 T53 = TPC12: room: CPU
T56-T59 T62 T63 T106 T108 = TPC12: room: PCH
T117 = TPC12: room: SIO
T142 T143 = TPC12: room: LAN
T156 = TAIMA_IH-115-F_24P
U2 = SLGC55584AVTR_TDFN8_2X2: room: USB
U6 = PI3V713-AZLEX_TQFN32_6X3
U8 = RT9818A-44GU3_SC70-3
U9 U50 = NL17SZ08DFT2G_SC70-5: room: KBC
U15 = NL17SZ08DFT2G_SC70-5: room: LAN
U19 = PS8401ATQFN40GTR-A3_TQFN40_5X5
U20 U23 = PI3C3125LEX_TSSOP14: room: DP_SW
U21 U24 = TC7SET04FU_SSOP5: room: DP_SW
U27 = RTD2136S-CG_QFN48_6X6
U31 = WGI217LM-QPN9-A2_QFN48_6X6: room: LAN
U32 = PI3L720ZHEX_TQFN42_9X3P5: room: LAN
U36 U37 U57 U145 U146 = TPS22966DPUR_SON14_2X3
U38 = OZ777FJ2LN_QFN48_6X6: room: OZ600
U39 = AT97SC3204-X2A14-AB_TSSOP28: room: TPM
U41 = TPS2231MRGPR-2_QFN20_4X4: room: EXPRESS
U46 = ECE5048-LZY_DQFN132_11X11: room: SIO
U48 = G547I2P81U_MSOP8: room: USB
U51 = MEC5075-LZY_DQFN132_11X11: room: KBC
U52 = W25Q64FVSSIQ_SO8: room: FLASH ROM
U53 = W25Q32FVSSIQ_SO8: room: FLASH ROM
U54 U56 UH2 = NL17SZ08DFT2G_SC70-5
U58 = NL17SZ08DFT2G_SC70-5: room: LED
U74 = ALC3226-CG_QFN48_7X7
U88 = LNG3DMTR_LGA16_3X3: room: HDD
U89 = AP2330W-7_SC59-3
U91 U93 = G547I2P81U_MSOP8
U148 = APL3512ABI-TRG_SOT23-5
UC1 = 74AHC1G09GW_TSSOP5: room: CPU
UC2 = SN74LVC1G07DCKR_SC70-5: room: CPU
UC3 = 74AHC1G09GW_TSSOP5
UH1 = DH82LPMS-QCG1-B0_FCBGA_695P
UH3 = NL17SZ08DFT2G_SC70-5: room: PCH
UV1 = 216-0841009-A0-SUN_FCBGA_631P: room: GPU
UV3-UV6 = K4G41325FC-HC04_FBGA_170P: room: GPU
UV14 = 74AHC1G09GW_TSSOP5: room: GPU
Y3 = Y_X3G025000DI1H-H_4P: room: LAN
Y6 = Y_Q13FC1350000_2P: room: KBC
YH1 = Y_Q13FC1350000_2P: room: PCH
YH2 = Y_Q22FA2380049900_4P: room: PCH
YV1 = Y_7V27000050_4P: room: GPU

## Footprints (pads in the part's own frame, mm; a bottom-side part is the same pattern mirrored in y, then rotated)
2N7002DW-T-R7_SOT363-6
  oval 0.381x1.397 smd: 1(0,0) 2(0.65,0) 3(1.3,0) 4(1.3,1.725) 5(0.65,1.725) 6(0,1.725)
74AHC1G09GW_TSSOP5
  oval 0.381x1.346 smd: 1(0,0) 2(0.65,0) 3(1.3,0) 4(1.3,1.79) 5(0,1.79)
216-0841009-A0-SUN_FCBGA_631P
  round 0.406 smd: A3(0.8,0) A30(20.8,0) A32(21.6,0) AB7(3.2,-15) AB8(4,-15) AB9(4.8,-15) AB10(5.6,-15) AB23(16,-15) AB24(16.8,-15) AB25(17.6,-15) AB26(18.4,-15) AC11(6.6,-16) AC13(7.8,-16) AC14(9,-16) AC16(10.2,-16) AC17(11.4,-16) AC19(12.6,-16) AC20(13.8,-16) AC22(15,-16) AD11(6.6,-16.8) AD13(7.8,-16.8) AD14(9,-16.8) AD16(10.2,-16.8) AD17(11.4,-16.8) AD19(12.6,-16.8) AD20(13.8,-16.8) AD22(15,-16.8) AE11(6.6,-17.6) AE13(7.8,-17.6) AE14(9,-17.6) AE16(10.2,-17.6) AE17(11.4,-17.6) AE19(12.6,-17.6) AE20(13.8,-17.6) AE22(15,-17.6) AF11(6.6,-18.4) AF13(7.8,-18.4) AF14(9,-18.4) AF16(10.2,-18.4) AF17(11.4,-18.4) AF19(12.6,-18.4) AF20(13.8,-18.4) AF22(15,-18.4) AK1(0,-20.8) AK3(0.8,-20.8) AK30(20.8,-20.8) AK32(21.6,-20.8) AM1(0,-21.6) AM3(0.8,-21.6) AM30(20.8,-21.6) AM32(21.6,-21.6) C1(0,-0.8) C3(0.8,-0.8) C30(20.8,-0.8) C32(21.6,-0.8) G11(6.6,-3.2) G13(7.8,-3.2) G14(9,-3.2) G16(10.2,-3.2) G17(11.4,-3.2) G19(12.6,-3.2) G20(13.8,-3.2) G22(15,-3.2) H11(6.6,-4) H13(7.8,-4) H14(9,-4) H16(10.2,-4) H17(11.4,-4) H19(12.6,-4) H20(13.8,-4) H22(15,-4) J11(6.6,-4.8) J13(7.8,-4.8) J14(9,-4.8) J16(10.2,-4.8) J17(11.4,-4.8) J19(12.6,-4.8) J20(13.8,-4.8) J22(15,-4.8) K11(6.6,-5.6) K13(7.8,-5.6) K14(9,-5.6) K16(10.2,-5.6) K17(11.4,-5.6) K19(12.6,-5.6) K20(13.8,-5.6) K22(15,-5.6) L7(3.2,-6.6) L8(4,-6.6) L9(4.8,-6.6) L10(5.6,-6.6) L23(16,-6.6) L24(16.8,-6.6) L25(17.6,-6.6) L26(18.4,-6.6) N7(3.2,-7.8) N8(4,-7.8) N9(4.8,-7.8) N10(5.6,-7.8) N23(16,-7.8) N24(16.8,-7.8) N25(17.6,-7.8) N26(18.4,-7.8) P7(3.2,-9) P8(4,-9) P9(4.8,-9) P10(5.6,-9) P23(16,-9) P24(16.8,-9) P25(17.6,-9) P26(18.4,-9) T7(3.2,-10.2) T8(4,-10.2) T9(4.8,-10.2) T10(5.6,-10.2) T23(16,-10.2) T24(16.8,-10.2) T25(17.6,-10.2) T26(18.4,-10.2) U7(3.2,-11.4) U8(4,-11.4) U9(4.8,-11.4) U10(5.6,-11.4) U23(16,-11.4) U24(16.8,-11.4) U25(17.6,-11.4) U26(18.4,-11.4) W7(3.2,-12.6) W8(4,-12.6) W9(4.8,-12.6) W10(5.6,-12.6) W23(16,-12.6) W24(16.8,-12.6) W25(17.6,-12.6) W26(18.4,-12.6) Y7(3.2,-13.8) Y8(4,-13.8) Y9(4.8,-13.8) Y10(5.6,-13.8) Y23(16,-13.8) Y24(16.8,-13.8) Y25(17.6,-13.8) Y26(18.4,-13.8)
  round 0.305 smd: A5(1.6,0) A7(3.2,0) A9(4.8,0) A11(6.4,0) A13(8,0) A15(9.6,0) A17(11.2,0) A19(12.8,0) A21(14.4,0) A23(16,0) A25(17.6,0) A27(19.2,0) A28(20,0) AA1(0,-14.4) AA3(0.8,-14.4) AA5(1.6,-14.4) AA6(2.4,-14.4) AA27(19.2,-14.4) AA29(20.4,-14.4) AA31(21.2,-14.4) AB2(0.4,-15.2) AB4(1.2,-15.2) AB6(2.4,-15.2) AB27(19.2,-15.2) AB28(20,-15.2) AB30(20.8,-15.2) AB32(21.6,-15.2) AC1(0,-16) AC3(0.8,-16) AC5(1.6,-16) AC6(2.4,-16) AC7(3.2,-16) AC8(4,-16) AC9(4.8,-16) AC10(5.6,-16) AC23(16,-16) AC24(16.8,-16) AC25(17.6,-16) AC26(18.4,-16) AC27(19.2,-16) AC29(20.4,-16) AC31(21.2,-16) AD2(0.4,-16.8) AD4(1.2,-16.8) AD6(2.4,-16.8) AD7(3.2,-16.8) AD8(4,-16.8) AD9(4.8,-16.8) AD10(5.6,-16.8) AD23(16,-16.8) AD24(16.8,-16.8) AD25(17.6,-16.8) AD26(18.4,-16.8) AD27(19.2,-16.8) AD28(20,-16.8) AD30(20.8,-16.8) AD32(21.6,-16.8) AE1(0,-17.6) AE3(0.8,-17.6) AE5(1.6,-17.6) AE6(2.4,-17.6) AE7(3.2,-17.6) AE8(4,-17.6) AE9(4.8,-17.6) AE10(5.6,-17.6) AE23(16,-17.6) AE24(16.8,-17.6) AE25(17.6,-17.6) AE26(18.4,-17.6) AE27(19.2,-17.6) AE29(20.4,-17.6) AE31(21.2,-17.6) AF2(0.4,-18.4) AF4(1.2,-18.4) AF6(2.4,-18.4) AF7(3.2,-18.4) AF8(4,-18.4) AF9(4.8,-18.4) AF10(5.6,-18.4) AF23(16,-18.4) AF24(16.8,-18.4) AF25(17.6,-18.4) AF26(18.4,-18.4) AF27(19.2,-18.4) AF28(20,-18.4) AF30(20.8,-18.4) AF32(21.6,-18.4) AG1(0,-19.2) AG3(0.8,-19.2) AG5(1.6,-19.2) AG6(2.4,-19.2) AG7(3.2,-19.2) AG8(4,-19.2) AG9(4.8,-19.2) AG10(5.6,-19.2) AG11(6.4,-19.2) AG12(7.2,-19.2) AG13(8,-19.2) AG14(8.8,-19.2) AG15(9.6,-19.2) AG16(10.4,-19.2) AG17(11.2,-19.2) AG18(12,-19.2) AG19(12.8,-19.2) AG20(13.6,-19.2) AG21(14.4,-19.2) AG22(15.2,-19.2) AG23(16,-19.2) AG24(16.8,-19.2) AG25(17.6,-19.2) AG26(18.4,-19.2) AG27(19.2,-19.2) AG29(20.4,-19.2) AG31(21.2,-19.2) AH1(0,-20) AH3(0.8,-20) AH5(1.6,-20) AH6(2.4,-20) AH8(4,-20) AH10(5.6,-20) AH12(7.2,-20) AH14(8.8,-20) AH16(10.4,-20) AH18(12,-20) AH20(13.6,-20) AH22(15.2,-20) AH24(16.8,-20) AH26(18.4,-20) AH28(20,-20) AH30(20.8,-20) AH32(21.6,-20) AJ7(3.2,-20.4) AJ9(4.8,-20.4) AJ11(6.4,-20.4) AJ13(8,-20.4) AJ15(9.6,-20.4) AJ17(11.2,-20.4) AJ19(12.8,-20.4) AJ21(14.4,-20.4) AJ23(16,-20.4) AJ25(17.6,-20.4) AJ27(19.2,-20.4) AK5(1.6,-20.8) AK6(2.4,-20.8) AK8(4,-20.8) AK10(5.6,-20.8) AK12(7.2,-20.8) AK14(8.8,-20.8) AK16(10.4,-20.8) AK18(12,-20.8) AK20(13.6,-20.8) AK22(15.2,-20.8) AK24(16.8,-20.8) AK26(18.4,-20.8) AK28(20,-20.8) AL7(3.2,-21.2) AL9(4.8,-21.2) AL11(6.4,-21.2) AL13(8,-21.2) AL15(9.6,-21.2) AL17(11.2,-21.2) AL19(12.8,-21.2) AL21(14.4,-21.2) AL23(16,-21.2) AL25(17.6,-21.2) AL27(19.2,-21.2) AM5(1.6,-21.6) AM6(2.4,-21.6) AM8(4,-21.6) AM10(5.6,-21.6) AM12(7.2,-21.6) AM14(8.8,-21.6) AM16(10.4,-21.6) AM18(12,-21.6) AM20(13.6,-21.6) AM22(15.2,-21.6) AM24(16.8,-21.6) AM26(18.4,-21.6) AM28(20,-21.6) B6(2.4,-0.4) B8(4,-0.4) B10(5.6,-0.4) B12(7.2,-0.4) B14(8.8,-0.4) B16(10.4,-0.4) B18(12,-0.4) B20(13.6,-0.4) B22(15.2,-0.4) B24(16.8,-0.4) B26(18.4,-0.4) C5(1.6,-0.8) C7(3.2,-0.8) C9(4.8,-0.8) C11(6.4,-0.8) C13(8,-0.8) C15(9.6,-0.8) C17(11.2,-0.8) C19(12.8,-0.8) C21(14.4,-0.8) C23(16,-0.8) C25(17.6,-0.8) C27(19.2,-0.8) C28(20,-0.8) D6(2.4,-1.2) D8(4,-1.2) D10(5.6,-1.2) D12(7.2,-1.2) D14(8.8,-1.2) D16(10.4,-1.2) D18(12,-1.2) D20(13.6,-1.2) D22(15.2,-1.2) D24(16.8,-1.2) D26(18.4,-1.2) E1(0,-1.6) E3(0.8,-1.6) E5(1.6,-1.6) E7(3.2,-1.6) E9(4.8,-1.6) E11(6.4,-1.6) E13(8,-1.6) E15(9.6,-1.6) E17(11.2,-1.6) E19(12.8,-1.6) E21(14.4,-1.6) E23(16,-1.6) E25(17.6,-1.6) E27(19.2,-1.6) E28(20,-1.6) E30(20.8,-1.6) E32(21.6,-1.6) F2(0.4,-2.4) F4(1.2,-2.4) F6(2.4,-2.4) F7(3.2,-2.4) F8(4,-2.4) F9(4.8,-2.4) F10(5.6,-2.4) F11(6.4,-2.4) F12(7.2,-2.4) F13(8,-2.4) F14(8.8,-2.4) F15(9.6,-2.4) F16(10.4,-2.4) F17(11.2,-2.4) F18(12,-2.4) F19(12.8,-2.4) F20(13.6,-2.4) F21(14.4,-2.4) F22(15.2,-2.4) F23(16,-2.4) F24(16.8,-2.4) F25(17.6,-2.4) F26(18.4,-2.4) F27(19.2,-2.4) F28(20,-2.4) F30(20.8,-2.4) F32(21.6,-2.4) G1(0,-3.2) G3(0.8,-3.2) G5(1.6,-3.2) G6(2.4,-3.2) G7(3.2,-3.2) G8(4,-3.2) G9(4.8,-3.2) G10(5.6,-3.2) G23(16,-3.2) G24(16.8,-3.2) G25(17.6,-3.2) G26(18.4,-3.2) G27(19.2,-3.2) G29(20.4,-3.2) G31(21.2,-3.2) H2(0.4,-4) H4(1.2,-4) H6(2.4,-4) H7(3.2,-4) H8(4,-4) H9(4.8,-4) H10(5.6,-4) H23(16,-4) H24(16.8,-4) H25(17.6,-4) H26(18.4,-4) H27(19.2,-4) H28(20,-4) H30(20.8,-4) H32(21.6,-4) J1(0,-4.8) J3(0.8,-4.8) J5(1.6,-4.8) J6(2.4,-4.8) J7(3.2,-4.8) J8(4,-4.8) J9(4.8,-4.8) J10(5.6,-4.8) J23(16,-4.8) J24(16.8,-4.8) J25(17.6,-4.8) J26(18.4,-4.8) J27(19.2,-4.8) J29(20.4,-4.8) J31(21.2,-4.8) K2(0.4,-5.6) K4(1.2,-5.6) K6(2.4,-5.6) K7(3.2,-5.6) K8(4,-5.6) K9(4.8,-5.6) K10(5.6,-5.6) K23(16,-5.6) K24(16.8,-5.6) K25(17.6,-5.6) K26(18.4,-5.6) K27(19.2,-5.6) K28(20,-5.6) K30(20.8,-5.6) K32(21.6,-5.6) L1(0,-6.4) L3(0.8,-6.4) L5(1.6,-6.4) L6(2.4,-6.4) L27(19.2,-6.4) L29(20.4,-6.4) L31(21.2,-6.4) M2(0.4,-7.2) M4(1.2,-7.2) M6(2.4,-7.2) M27(19.2,-7.2) M28(20,-7.2) M30(20.8,-7.2) M32(21.6,-7.2) N1(0,-8) N3(0.8,-8) N5(1.6,-8) N6(2.4,-8) N27(19.2,-8) N29(20.4,-8) N31(21.2,-8) P2(0.4,-8.8) P4(1.2,-8.8) P6(2.4,-8.8) P27(19.2,-8.8) P28(20,-8.8) P30(20.8,-8.8) P32(21.6,-8.8) R1(0,-9.6) R3(0.8,-9.6) R5(1.6,-9.6) R6(2.4,-9.6) R27(19.2,-9.6) R29(20.4,-9.6) R31(21.2,-9.6) T2(0.4,-10.4) T4(1.2,-10.4) T6(2.4,-10.4) T27(19.2,-10.4) T28(20,-10.4) T30(20.8,-10.4) T32(21.6,-10.4) U1(0,-11.2) U3(0.8,-11.2) U5(1.6,-11.2) U6(2.4,-11.2) U27(19.2,-11.2) U29(20.4,-11.2) U31(21.2,-11.2) V2(0.4,-12) V4(1.2,-12) V6(2.4,-12) V27(19.2,-12) V28(20,-12) V30(20.8,-12) V32(21.6,-12) W1(0,-12.8) W3(0.8,-12.8) W5(1.6,-12.8) W6(2.4,-12.8) W27(19.2,-12.8) W29(20.4,-12.8) W31(21.2,-12.8) Y2(0.4,-13.6) Y4(1.2,-13.6) Y6(2.4,-13.6) Y27(19.2,-13.6) Y28(20,-13.6) Y30(20.8,-13.6) Y32(21.6,-13.6)
  round 0.508 smd: AA11(6.4,-14.2) AA12(7.4,-14.2) AA13(8.4,-14.2) AA15(9.4,-14.2) AA16(10.4,-14.2) AA17(11.2,-14.2) AA18(12.2,-14.2) AA20(13.2,-14.2) AA21(14.2,-14.2) AA22(15.2,-14.2) AB11(6.4,-15.2) AB12(7.4,-15.2) AB13(8.4,-15.2) AB15(9.4,-15.2) AB16(10.4,-15.2) AB17(11.2,-15.2) AB18(12.2,-15.2) AB20(13.2,-15.2) AB21(14.2,-15.2) AB22(15.2,-15.2) L11(6.4,-6.4) L12(7.4,-6.4) L13(8.4,-6.4) L15(9.4,-6.4) L16(10.4,-6.4) L17(11.2,-6.4) L18(12.2,-6.4) L20(13.2,-6.4) L21(14.2,-6.4) L22(15.2,-6.4) M11(6.4,-7.4) M12(7.4,-7.4) M13(8.4,-7.4) M15(9.4,-7.4) M16(10.4,-7.4) M17(11.2,-7.4) M18(12.2,-7.4) M20(13.2,-7.4) M21(14.2,-7.4) M22(15.2,-7.4) N11(6.4,-8.4) N12(7.4,-8.4) N13(8.4,-8.4) N15(9.4,-8.4) N16(10.4,-8.4) N17(11.2,-8.4) N18(12.2,-8.4) N20(13.2,-8.4) N21(14.2,-8.4) N22(15.2,-8.4) R11(6.4,-9.4) R12(7.4,-9.4) R13(8.4,-9.4) R15(9.4,-9.4) R16(10.4,-9.4) R17(11.2,-9.4) R18(12.2,-9.4) R20(13.2,-9.4) R21(14.2,-9.4) R22(15.2,-9.4) T11(6.4,-10.4) T12(7.4,-10.4) T13(8.4,-10.4) T15(9.4,-10.4) T16(10.4,-10.4) T17(11.2,-10.4) T18(12.2,-10.4) T20(13.2,-10.4) T21(14.2,-10.4) T22(15.2,-10.4) U11(6.4,-11.2) U12(7.4,-11.2) U13(8.4,-11.2) U15(9.4,-11.2) U16(10.4,-11.2) U17(11.2,-11.2) U18(12.2,-11.2) U20(13.2,-11.2) U21(14.2,-11.2) U22(15.2,-11.2) V11(6.4,-12.2) V12(7.4,-12.2) V13(8.4,-12.2) V15(9.4,-12.2) V16(10.4,-12.2) V17(11.2,-12.2) V18(12.2,-12.2) V20(13.2,-12.2) V21(14.2,-12.2) V22(15.2,-12.2) Y11(6.4,-13.2) Y12(7.4,-13.2) Y13(8.4,-13.2) Y15(9.4,-13.2) Y16(10.4,-13.2) Y17(11.2,-13.2) Y18(12.2,-13.2) Y20(13.2,-13.2) Y21(14.2,-13.2) Y22(15.2,-13.2)
